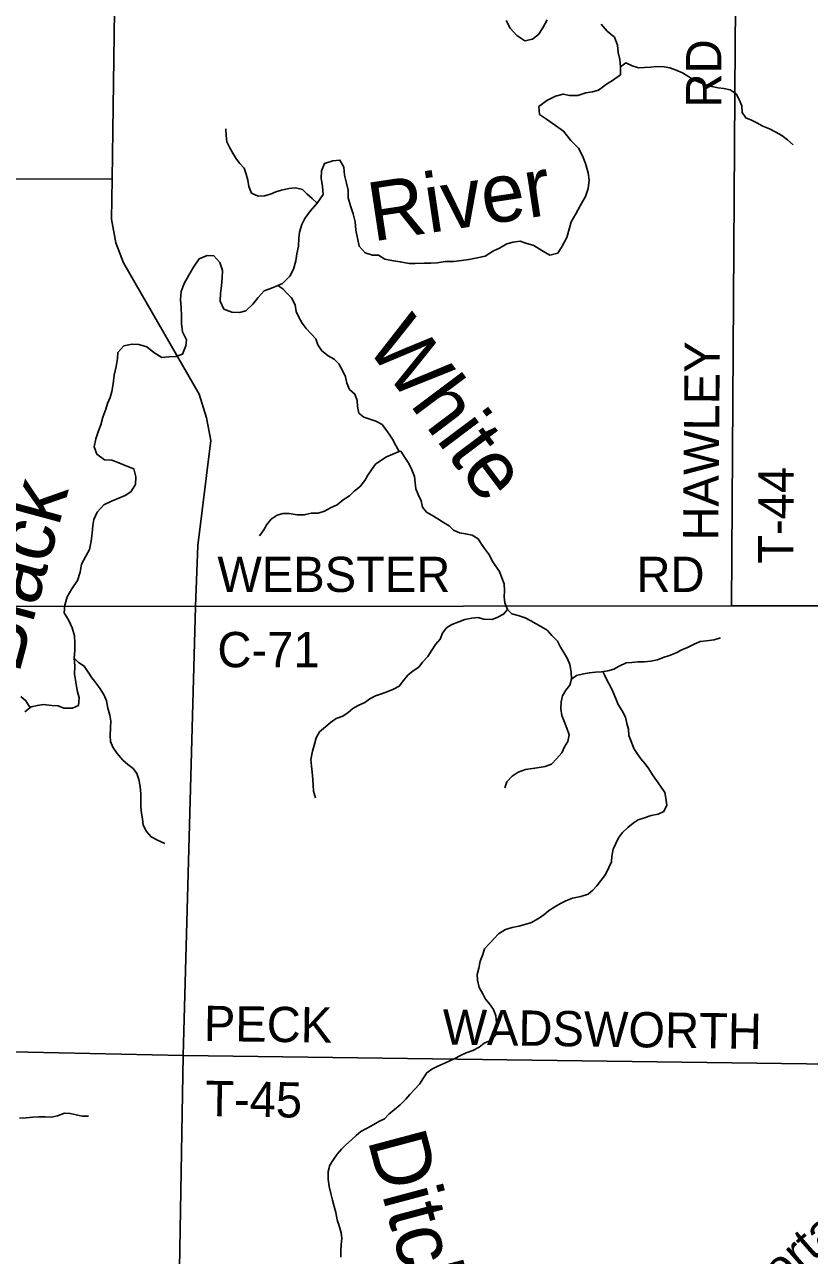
# Model space of a CAD drawing. Extents: x 1857828 to 2277390, y 930619 to 1324581.
# Drawn here: x 2045060 to 2051743, y 1160303 to 1170776 of the extents above; entities that cross this region are included whole.
import ezdxf

# ---------------------------------------------------------------- set-up
doc = ezdxf.new("R2010")
doc.units = 0
for name, color, linetype in [('GM_X_County_Road', 7, 'Continuous'), ('GM_X_County_Road_Text', 7, 'Continuous'), ('GM_X_Major_River', 7, 'Continuous'), ('GM_X_Major_River_Text', 7, 'Continuous'), ('GM_X_Minor_River', 7, 'Continuous'), ('GM_X_Minor_River_Text', 7, 'Continuous'), ('GM_X_Rail_Line_Text', 7, 'Continuous'), ('GM_X_State_Route', 7, 'Continuous'), ('GM_X_Township', 7, 'Continuous'), ('GM_X_Township_Road', 7, 'Continuous'), ('GM_X_Township_Road_Text', 7, 'Continuous')]:
    doc.layers.add(name, color=color, linetype=linetype)

msp = doc.modelspace()

# ---------------------------------------------------------------- linework, layer by layer
at = {"layer": 'GM_X_County_Road'}
for points in [[(2046516, 1165826), (2051080, 1165830), (2053083, 1165829), (2056293, 1165821), (2059723, 1165822)], [(2044561, 1162043), (2046410, 1162005)]]:
    msp.add_lwpolyline(points, dxfattribs=at)
at = {"layer": 'GM_X_Major_River'}
for points in [[(2049510, 1170817), (2049474, 1170747), (2049437, 1170691), (2049385, 1170653), (2049321, 1170637), (2049252, 1170683), (2049196, 1170746), (2049160, 1170812)], [(2050136, 1170417), (2050130, 1170478), (2050116, 1170538), (2050108, 1170600), (2050084, 1170668), (2050022, 1170721), (2049970, 1170781)], [(2047216, 1168557), (2047256, 1168573), (2047318, 1168635), (2047349, 1168695), (2047369, 1168766), (2047379, 1168826), (2047394, 1168892), (2047396, 1168960), (2047400, 1169010), (2047420, 1169076), (2047447, 1169126), (2047491, 1169188), (2047551, 1169257), (2047604, 1169329), (2047596, 1169401), (2047586, 1169465), (2047589, 1169533), (2047615, 1169595), (2047685, 1169617), (2047746, 1169623), (2047778, 1169563), (2047785, 1169494), (2047801, 1169426), (2047817, 1169366), (2047817, 1169302), (2047835, 1169235), (2047857, 1169165), (2047875, 1169097), (2047882, 1169027), (2047894, 1168958), (2047908, 1168890), (2047960, 1168834), (2048024, 1168815), (2048075, 1168813), (2048129, 1168779), (2048201, 1168765), (2048259, 1168758), (2048334, 1168744), (2048386, 1168744), (2048462, 1168746), (2048519, 1168746), (2048573, 1168749), (2048643, 1168761), (2048716, 1168761), (2048780, 1168769), (2048844, 1168777), (2048915, 1168790), (2048983, 1168806), (2049054, 1168852), (2049104, 1168874), (2049168, 1168910), (2049221, 1168924), (2049279, 1168932), (2049329, 1168915), (2049397, 1168895), (2049464, 1168853), (2049532, 1168814), (2049600, 1168830), (2049637, 1168892), (2049677, 1168964), (2049699, 1169036), (2049716, 1169097), (2049754, 1169167), (2049792, 1169233), (2049837, 1169313), (2049859, 1169381), (2049867, 1169453), (2049858, 1169515), (2049838, 1169594), (2049810, 1169658), (2049776, 1169724), (2049712, 1169791), (2049648, 1169869), (2049582, 1169918), (2049505, 1169972), (2049445, 1170012), (2049439, 1170079), (2049506, 1170131), (2049580, 1170166), (2049647, 1170184), (2049701, 1170174), (2049771, 1170174), (2049840, 1170194), (2049896, 1170205), (2049946, 1170219), (2050015, 1170269), (2050067, 1170299), (2050134, 1170349), (2050136, 1170417)], [(2045061, 1164928), (2045116, 1164970), (2045170, 1164983), (2045220, 1164991), (2045293, 1164983), (2045345, 1164979), (2045395, 1164959), (2045468, 1164960), (2045518, 1164982), (2045524, 1165048), (2045508, 1165111), (2045496, 1165181), (2045485, 1165249), (2045489, 1165321), (2045483, 1165384), (2045489, 1165450), (2045487, 1165514), (2045486, 1165574), (2045464, 1165642), (2045436, 1165705), (2045398, 1165771), (2045402, 1165837), (2045424, 1165907), (2045463, 1165975), (2045511, 1166045), (2045534, 1166118), (2045544, 1166184), (2045582, 1166252), (2045613, 1166310), (2045627, 1166380), (2045635, 1166448), (2045641, 1166514), (2045650, 1166565), (2045678, 1166627), (2045734, 1166691), (2045799, 1166721), (2045849, 1166742), (2045916, 1166770), (2045966, 1166800), (2046004, 1166864), (2046008, 1166928), (2045989, 1166997), (2045930, 1167019), (2045862, 1167047), (2045802, 1167070), (2045742, 1167074), (2045675, 1167120), (2045652, 1167184), (2045668, 1167251), (2045690, 1167319), (2045710, 1167369), (2045727, 1167437), (2045751, 1167503), (2045767, 1167553), (2045788, 1167603), (2045802, 1167653), (2045814, 1167720), (2045822, 1167794), (2045841, 1167866), (2045851, 1167936), (2045855, 1167986), (2045906, 1168044), (2045976, 1168058), (2046034, 1168054), (2046102, 1168034), (2046161, 1167985), (2046229, 1167943), (2046289, 1167949), (2046347, 1167951), (2046406, 1167972), (2046434, 1168043), (2046438, 1168095), (2046404, 1168163), (2046397, 1168233), (2046395, 1168297), (2046393, 1168366), (2046387, 1168436), (2046393, 1168506), (2046420, 1168574), (2046460, 1168644), (2046499, 1168712), (2046547, 1168782), (2046615, 1168812), (2046672, 1168808), (2046724, 1168752), (2046746, 1168683), (2046743, 1168621), (2046737, 1168555), (2046729, 1168489), (2046727, 1168423), (2046757, 1168356), (2046825, 1168328), (2046889, 1168326), (2046944, 1168340), (2047004, 1168396), (2047050, 1168454), (2047101, 1168512), (2047163, 1168532), (2047216, 1168557)]]:
    msp.add_lwpolyline(points, dxfattribs=at)
at = {"layer": 'GM_X_Minor_River'}
for points in [[(2050136, 1170417), (2050180, 1170450), (2050233, 1170424), (2050289, 1170408), (2050339, 1170410), (2050393, 1170414), (2050446, 1170419), (2050506, 1170417), (2050556, 1170409), (2050608, 1170387), (2050663, 1170366), (2050709, 1170338), (2050755, 1170306), (2050809, 1170284), (2050861, 1170263), (2050912, 1170249), (2050966, 1170239), (2051016, 1170231), (2051070, 1170220), (2051119, 1170188), (2051145, 1170140), (2051169, 1170086), (2051170, 1170029), (2051202, 1169983), (2051249, 1169963), (2051297, 1169941), (2051347, 1169912), (2051403, 1169888), (2051457, 1169862), (2051508, 1169831), (2051556, 1169795), (2051606, 1169753)], [(2047551, 1169257), (2047510, 1169295), (2047464, 1169337), (2047426, 1169373), (2047366, 1169386), (2047311, 1169382), (2047249, 1169368), (2047201, 1169352), (2047154, 1169332), (2047104, 1169318), (2047050, 1169315), (2046993, 1169343), (2046971, 1169397), (2046960, 1169451), (2046948, 1169502), (2046930, 1169554), (2046890, 1169598), (2046858, 1169638), (2046834, 1169683), (2046808, 1169727), (2046782, 1169777), (2046778, 1169831), (2046774, 1169888)], [(2047216, 1168557), (2047260, 1168529), (2047294, 1168491), (2047334, 1168451), (2047364, 1168392), (2047374, 1168336), (2047396, 1168286), (2047424, 1168236), (2047458, 1168191), (2047500, 1168145), (2047540, 1168103), (2047558, 1168050), (2047592, 1168000), (2047646, 1167958), (2047695, 1167928), (2047735, 1167889), (2047767, 1167833), (2047793, 1167779), (2047803, 1167724), (2047826, 1167672), (2047873, 1167632), (2047893, 1167578), (2047896, 1167525), (2047906, 1167471), (2047948, 1167437), (2048001, 1167419), (2048051, 1167402), (2048105, 1167372), (2048135, 1167332), (2048165, 1167292), (2048193, 1167249), (2048221, 1167195), (2048249, 1167143)], [(2048249, 1167143), (2048195, 1167121), (2048142, 1167099), (2048094, 1167067), (2048048, 1167035), (2048015, 1166987), (2047983, 1166941), (2047957, 1166897), (2047916, 1166843), (2047866, 1166805), (2047826, 1166767), (2047773, 1166731), (2047723, 1166689), (2047670, 1166666), (2047614, 1166636), (2047560, 1166620), (2047501, 1166618), (2047441, 1166604), (2047381, 1166606), (2047314, 1166615), (2047260, 1166615), (2047210, 1166603), (2047161, 1166567), (2047123, 1166523), (2047097, 1166477), (2047060, 1166427)], [(2048249, 1167143), (2048265, 1167145), (2048299, 1167093), (2048333, 1167042), (2048357, 1166988), (2048381, 1166932), (2048387, 1166878), (2048393, 1166827), (2048413, 1166779), (2048437, 1166723), (2048449, 1166671), (2048483, 1166628), (2048527, 1166602), (2048579, 1166570), (2048627, 1166538), (2048675, 1166511), (2048713, 1166475), (2048764, 1166451), (2048816, 1166444), (2048872, 1166432), (2048924, 1166400), (2048950, 1166356), (2048986, 1166307), (2049020, 1166261), (2049042, 1166213), (2049070, 1166171), (2049104, 1166122), (2049124, 1166068), (2049144, 1166018), (2049148, 1165958), (2049144, 1165908), (2049150, 1165857), (2049172, 1165799)], [(2049172, 1165799), (2049139, 1165759), (2049089, 1165733), (2049041, 1165713), (2048972, 1165716), (2048920, 1165730), (2048868, 1165726), (2048809, 1165714), (2048757, 1165694), (2048699, 1165672), (2048652, 1165643), (2048618, 1165597), (2048598, 1165546), (2048559, 1165500), (2048529, 1165452), (2048493, 1165400), (2048450, 1165352), (2048416, 1165308), (2048370, 1165278), (2048323, 1165240), (2048287, 1165194), (2048251, 1165146), (2048202, 1165121), (2048154, 1165101), (2048100, 1165081), (2048047, 1165065), (2048001, 1165039), (2047957, 1165007), (2047902, 1164983), (2047854, 1164957), (2047815, 1164923), (2047769, 1164891), (2047713, 1164872), (2047664, 1164838), (2047622, 1164800), (2047572, 1164758), (2047543, 1164708), (2047529, 1164654), (2047513, 1164594), (2047498, 1164523), (2047502, 1164465), (2047508, 1164415), (2047514, 1164353), (2047518, 1164303), (2047520, 1164252), (2047538, 1164196)], [(2049172, 1165799), (2049210, 1165761), (2049264, 1165749), (2049322, 1165728), (2049371, 1165702), (2049417, 1165678), (2049463, 1165651), (2049509, 1165623), (2049551, 1165577), (2049597, 1165531), (2049623, 1165480), (2049653, 1165432), (2049683, 1165380), (2049703, 1165330), (2049715, 1165267), (2049717, 1165207), (2049703, 1165155), (2049668, 1165113), (2049640, 1165065), (2049630, 1165013), (2049627, 1164955), (2049635, 1164898), (2049657, 1164840), (2049677, 1164790), (2049699, 1164732), (2049687, 1164676), (2049659, 1164631), (2049636, 1164579), (2049590, 1164529), (2049548, 1164483), (2049493, 1164462), (2049441, 1164454), (2049385, 1164446), (2049326, 1164438), (2049262, 1164414), (2049211, 1164382), (2049167, 1164334), (2049149, 1164282)], [(2049717, 1165207), (2049759, 1165237), (2049820, 1165251), (2049870, 1165261), (2049922, 1165267), (2049974, 1165270), (2050027, 1165276), (2050079, 1165292), (2050123, 1165318), (2050182, 1165346), (2050232, 1165348), (2050282, 1165353), (2050335, 1165353), (2050393, 1165359), (2050449, 1165371), (2050498, 1165391), (2050552, 1165409), (2050608, 1165430), (2050657, 1165456), (2050705, 1165476), (2050755, 1165500), (2050812, 1165526), (2050866, 1165532), (2050931, 1165542), (2050987, 1165557)], [(2045483, 1165384), (2045520, 1165347), (2045568, 1165317), (2045602, 1165265), (2045633, 1165219), (2045667, 1165174), (2045703, 1165124), (2045737, 1165070), (2045757, 1165022), (2045768, 1164961), (2045786, 1164901), (2045794, 1164849), (2045792, 1164791), (2045788, 1164728), (2045792, 1164676), (2045812, 1164628), (2045848, 1164574), (2045898, 1164517), (2045938, 1164479), (2045984, 1164447), (2046016, 1164405), (2046034, 1164354), (2046044, 1164292), (2046050, 1164230), (2046049, 1164176), (2046049, 1164120), (2046055, 1164067), (2046063, 1164017), (2046069, 1163963), (2046099, 1163909), (2046137, 1163866), (2046193, 1163836), (2046253, 1163808)], [(2049984, 1165271), (2049984, 1165271), (2049998, 1165244), (2050022, 1165194), (2050046, 1165150), (2050070, 1165101), (2050092, 1165047), (2050114, 1164991), (2050148, 1164937), (2050178, 1164882), (2050190, 1164830), (2050204, 1164782), (2050206, 1164728), (2050228, 1164669), (2050248, 1164617), (2050278, 1164573), (2050308, 1164529), (2050344, 1164486), (2050376, 1164442), (2050406, 1164392), (2050442, 1164344), (2050476, 1164295), (2050512, 1164243), (2050522, 1164193), (2050530, 1164135), (2050505, 1164081), (2050455, 1164057), (2050397, 1164045), (2050340, 1164027), (2050286, 1164009), (2050244, 1163981), (2050197, 1163943), (2050153, 1163903), (2050117, 1163855), (2050094, 1163809), (2050072, 1163761), (2050060, 1163701), (2050058, 1163651), (2050035, 1163603), (2050007, 1163543), (2049971, 1163495), (2049934, 1163449), (2049900, 1163411), (2049858, 1163377), (2049797, 1163357), (2049727, 1163343), (2049670, 1163319), (2049624, 1163297), (2049576, 1163270), (2049521, 1163234), (2049479, 1163198), (2049431, 1163168), (2049376, 1163136), (2049320, 1163118), (2049268, 1163104), (2049211, 1163094), (2049155, 1163075), (2049096, 1163039), (2049058, 1162999), (2049020, 1162957), (2048977, 1162911), (2048963, 1162863), (2048941, 1162808), (2048928, 1162748), (2048914, 1162694), (2048916, 1162644), (2048932, 1162584), (2048962, 1162530), (2048984, 1162483), (2049020, 1162445), (2049054, 1162397), (2049074, 1162341), (2049078, 1162286), (2049078, 1162236), (2049073, 1162180), (2049033, 1162136), (2048975, 1162110), (2048930, 1162076), (2048878, 1162048), (2048820, 1162027), (2048771, 1162005), (2048723, 1161979), (2048675, 1161955), (2048624, 1161933), (2048574, 1161911), (2048528, 1161887), (2048485, 1161857), (2048457, 1161813), (2048423, 1161761), (2048382, 1161717), (2048342, 1161673), (2048307, 1161633), (2048259, 1161585), (2048209, 1161545), (2048162, 1161505), (2048124, 1161465), (2048076, 1161444), (2048033, 1161416), (2047973, 1161384), (2047924, 1161358), (2047884, 1161324)], [(2045109, 1164965), (2045099, 1164976), (2045071, 1165022), (2045029, 1165060)], [(2045017, 1161471), (2045073, 1161473), (2045130, 1161479), (2045180, 1161483), (2045234, 1161481), (2045290, 1161480), (2045341, 1161492), (2045399, 1161514), (2045449, 1161510), (2045500, 1161500), (2045550, 1161489), (2045604, 1161487)], [(2047884, 1161324), (2047844, 1161286), (2047795, 1161244), (2047759, 1161208), (2047723, 1161166), (2047690, 1161120), (2047660, 1161070), (2047646, 1161016), (2047646, 1160952), (2047653, 1160889), (2047667, 1160831), (2047681, 1160773), (2047697, 1160719), (2047711, 1160669), (2047721, 1160606), (2047739, 1160556), (2047757, 1160496), (2047761, 1160446), (2047756, 1160396), (2047752, 1160341), (2047754, 1160289)]]:
    msp.add_lwpolyline(points, dxfattribs=at)
at = {"layer": 'GM_X_State_Route'}
msp.add_lwpolyline([(2046379, 1160192), (2046410, 1162005), (2046516, 1165826), (2046535, 1166343), (2046647, 1167236), (2046610, 1167430), (2046548, 1167630), (2045903, 1168749), (2045837, 1168919), (2045801, 1169120), (2045806, 1169462), (2045875, 1174371), (2045906, 1176582), (2045974, 1179274)], dxfattribs=at)
at = {"layer": 'GM_X_Township'}
msp.add_lwpolyline([(2032206, 1165870), (2032243, 1167507), (2032281, 1179371), (2032309, 1188668), (2032348, 1192998), (2035009, 1192996), (2046211, 1193046), (2052905, 1193059), (2052996, 1193078), (2056703, 1193080), (2060043, 1193100), (2060012, 1189567), (2060011, 1189355), (2059891, 1179593), (2059723, 1165822), (2056293, 1165821), (2053083, 1165829), (2051080, 1165830), (2046516, 1165826), (2039516, 1165835), (2032339, 1165871)], close=True, dxfattribs=at)
msp.add_lwpolyline([(2032187, 1160189), (2032191, 1160394), (2032191, 1160469), (2032202, 1162261), (2032206, 1165870), (2032339, 1165871), (2039516, 1165835), (2046516, 1165826), (2051080, 1165830), (2053083, 1165829), (2056293, 1165821), (2059723, 1165822), (2059673, 1162156), (2059668, 1161839), (2059568, 1154416)], dxfattribs=at)
at = {"layer": 'GM_X_Township_Road'}
for points in [[(2051080, 1165830), (2051112, 1170609), (2051113, 1170907), (2051110, 1171056), (2051111, 1171325), (2051112, 1171595), (2051113, 1171928), (2051118, 1172135), (2051127, 1172490), (2051136, 1172799), (2051166, 1174447)], [(2040834, 1169478), (2045806, 1169462)], [(2046410, 1162005), (2052992, 1161916)]]:
    msp.add_lwpolyline(points, dxfattribs=at)

# ---------------------------------------------------------------- texts
at = {"layer": 'GM_X_County_Road_Text'}
for s, p in [('WEBSTER', (2046702, 1165948)), ('RD', (2050271, 1165948)), ('C-71', (2046702, 1165308))]:
    msp.add_text(s, height=300, rotation=0, dxfattribs=at).set_placement(p)
at = {"layer": 'GM_X_Major_River_Text'}
for s, rotation, p in [('River', 8.5555, (2048025, 1168930)), ('Black', 74.9039, (2045011, 1165242))]:
    msp.add_text(s, height=500.2, rotation=rotation, dxfattribs=at).set_placement(p)
at = {"layer": 'GM_X_Minor_River_Text'}
for s, rotation, p in [('White', 306.9059, (2047957, 1168046)), ('Ditch', 284.9067, (2047979, 1161289))]:
    msp.add_text(s, height=500.2, rotation=rotation, dxfattribs=at).set_placement(p)
at = {"layer": 'GM_X_Rail_Line_Text'}
msp.add_text('Transportation,', height=299, rotation=41.2571, dxfattribs=at).set_placement((2050572, 1159196))
at = {"layer": 'GM_X_Township_Road_Text'}
for s, rotation, p in [('RD', 90, (2050993, 1170071)), ('HAWLEY', 89.5241, (2050967, 1166385)), ('T-44', 89.6465, (2051605, 1166187)), ('PECK', 359.1925, (2046585, 1162128)), ('WADSWORTH', 359.1831, (2048618, 1162098)), ('T-45', 358.9383, (2046596, 1161490))]:
    msp.add_text(s, height=300, rotation=rotation, dxfattribs=at).set_placement(p)

doc.saveas('drawing.dxf')
